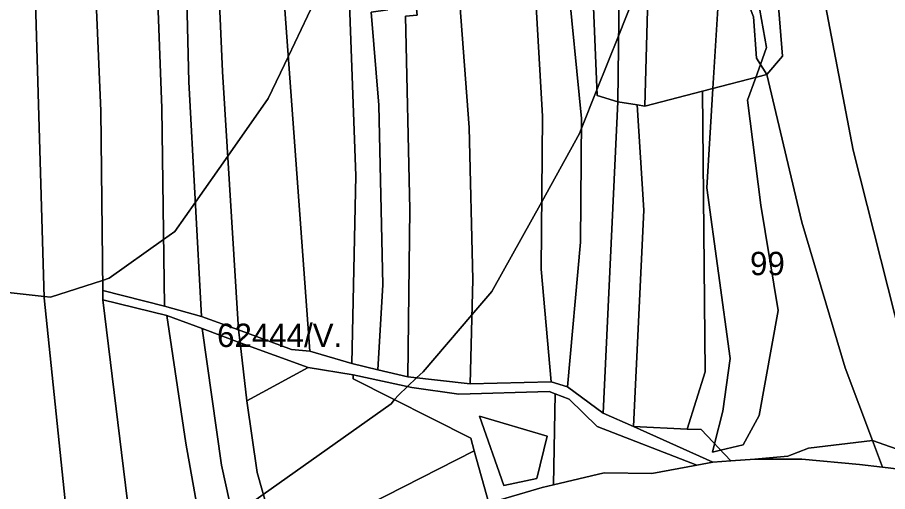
# Model space of a CAD drawing. Extents: x -502026 to -497664, y -1143484 to -1138019.
# Drawn here: x -499847.9 to -499550.1, y -1140485 to -1140322.7 of the extents above; entities that cross this region are included whole.
import ezdxf

# ---------------------------------------------------------------- set-up
doc = ezdxf.new("R2010")
doc.units = 0
for name, color, linetype in [('25', 7, 'Continuous'), ('37', 7, 'Continuous'), ('43', 7, 'Continuous'), ('55', 7, 'Continuous'), ('62', 7, 'Continuous'), ('7', 7, 'Continuous')]:
    doc.layers.add(name, color=color, linetype=linetype)

msp = doc.modelspace()

# ---------------------------------------------------------------- linework, layer by layer
at = {"layer": '25'}
msp.add_lwpolyline([(-499686.58, -1140489.01), (-499687.43, -1140489.26), (-499712.26, -1140501.49), (-499740.35, -1140520.01), (-499751.82, -1140528.09), (-499758.34, -1140505.08), (-499691.53, -1140471.05)], close=True, dxfattribs=at)
at = {"layer": '37'}
for points in [[(-499748.39, -1140442.56), (-499769.37, -1140453.89), (-499771.66, -1140434.1)], [(-499733.01, -1140445.05), (-499732.91, -1140446.38), (-499692.74, -1140466.67), (-499691.53, -1140471.05), (-499758.34, -1140505.08), (-499765.87, -1140478.52), (-499769.37, -1140453.89), (-499748.39, -1140442.56)], [(-499663.84, -1140451.56), (-499664.4, -1140482.72), (-499668.31, -1140483.66), (-499686.58, -1140489.01), (-499691.53, -1140471.05), (-499692.74, -1140466.67), (-499732.91, -1140446.38), (-499733.01, -1140445.05), (-499712.89, -1140449.42), (-499696.79, -1140451.71), (-499665.93, -1140450.77)], [(-499615.38, -1140475.96), (-499630.81, -1140478.84), (-499647.11, -1140478.54), (-499664.4, -1140482.72), (-499663.84, -1140451.56), (-499659.08, -1140453.37), (-499649.52, -1140462.72)], [(-499670.09, -1140480.49), (-499666.56, -1140466.05), (-499689.72, -1140459.19), (-499681.41, -1140482.88)], [(-499670.09, -1140480.49), (-499681.41, -1140482.88), (-499689.72, -1140459.19), (-499666.56, -1140466.05)]]:
    msp.add_lwpolyline(points, close=True, dxfattribs=at)
at = {"layer": '43'}
for points in [[(-499596.35, -1140204.84), (-499584.12, -1140216.73), (-499593.72, -1140236.53), (-499596.1, -1140251.93), (-499595.47, -1140264.79), (-499590.61, -1140280.33), (-499595.31, -1140290.27), (-499600.47, -1140311.03), (-499596.02, -1140322.53), (-499594.91, -1140336.66), (-499591.45, -1140342.31), (-499613.38, -1140347.92), (-499633.22, -1140353.08), (-499631.36, -1140287.08), (-499634.66, -1140229.73), (-499620.88, -1140231.06), (-499606.94, -1140230.49), (-499604.13, -1140197.28)], [(-499579.07, -1140255.16), (-499572.88, -1140310.74), (-499561.93, -1140368.15), (-499535.71, -1140471.44), (-499534.9, -1140474.68), (-499555.3, -1140467.53), (-499564.59, -1140442.61), (-499579.44, -1140392.82), (-499591.45, -1140342.31), (-499586.11, -1140335.99), (-499587.69, -1140315.99), (-499590.87, -1140299.36), (-499585.23, -1140286.97), (-499593.6, -1140252.66)], [(-499555.3, -1140467.53), (-499577.2, -1140470.15), (-499584.23, -1140472.85), (-499595.5, -1140473.95), (-499603.79, -1140474.51), (-499613.94, -1140463.81), (-499618.63, -1140463.6), (-499612.5, -1140444.05), (-499613.38, -1140347.92), (-499591.45, -1140342.31), (-499579.44, -1140392.82), (-499564.59, -1140442.61)], [(-499618.63, -1140463.6), (-499637, -1140462.77), (-499633.55, -1140388.66), (-499635.78, -1140352.66), (-499633.22, -1140353.08), (-499613.38, -1140347.92), (-499612.5, -1140444.05)]]:
    msp.add_lwpolyline(points, close=True, dxfattribs=at)
at = {"layer": '55'}
for points in [[(-499581.13, -1140219.7), (-499579.07, -1140255.16), (-499593.6, -1140252.66), (-499585.23, -1140286.97), (-499590.87, -1140299.36), (-499587.69, -1140315.99), (-499586.11, -1140335.99), (-499591.45, -1140342.31), (-499594.91, -1140336.66), (-499596.02, -1140322.53), (-499600.47, -1140311.03), (-499595.31, -1140290.27), (-499590.61, -1140280.33), (-499595.47, -1140264.79), (-499596.1, -1140251.93), (-499593.72, -1140236.53), (-499584.12, -1140216.73)], [(-499618.63, -1140463.6), (-499613.94, -1140463.81), (-499603.79, -1140474.51), (-499609.85, -1140474.92), (-499637, -1140462.77)], [(-499551.88, -1140476.7), (-499559.75, -1140475.77), (-499579.39, -1140473.94), (-499595.5, -1140473.95), (-499584.23, -1140472.85), (-499577.2, -1140470.15), (-499555.3, -1140467.53)], [(-499534.9, -1140474.68), (-499533.86, -1140478.84), (-499551.88, -1140476.7), (-499555.3, -1140467.53)]]:
    msp.add_lwpolyline(points, close=True, dxfattribs=at)
msp.add_lwpolyline([(-499686.58, -1140489.01), (-499668.31, -1140483.66), (-499664.4, -1140482.72), (-499647.11, -1140478.54), (-499630.81, -1140478.84), (-499615.38, -1140475.96), (-499609.85, -1140474.92), (-499603.79, -1140474.51), (-499595.5, -1140473.95), (-499579.39, -1140473.94), (-499559.75, -1140475.77), (-499551.88, -1140476.7), (-499533.86, -1140478.84)], dxfattribs=at)
at = {"layer": '62'}
for points in [[(-499605, -1140268.5), (-499609.89, -1140347.03), (-499612, -1140381), (-499604, -1140439.5), (-499606.5, -1140457.5), (-499609.3, -1140468.7), (-499610, -1140471.5), (-499607.26, -1140470.85), (-499599.5, -1140469), (-499594, -1140459), (-499587.5, -1140423), (-499593.5, -1140387), (-499598, -1140351), (-499595.21, -1140343.27), (-499593.6, -1140338.8), (-499591.5, -1140333), (-499595.5, -1140310.5)], [(-499595.5, -1140310.5), (-499591.5, -1140333), (-499593.6, -1140338.8), (-499595.21, -1140343.27), (-499598, -1140351), (-499593.5, -1140387), (-499587.5, -1140423), (-499594, -1140459), (-499599.5, -1140469), (-499607.26, -1140470.85), (-499610, -1140471.5), (-499609.3, -1140468.7), (-499606.5, -1140457.5), (-499604, -1140439.5), (-499612, -1140381), (-499609.89, -1140347.03), (-499605, -1140268.5)], [(-499735.62, -1140294.77), (-499755.15, -1140336.03), (-499762, -1140350.5), (-499775.89, -1140370.24), (-499786.96, -1140385.99), (-499794, -1140396), (-499797.84, -1140398.73), (-499816.5, -1140412), (-499818.7, -1140412.72), (-499836.5, -1140418.5), (-499838.7, -1140418.25), (-499857.26, -1140416.14), (-499858.5, -1140416), (-499872.5, -1140409.5), (-499878.74, -1140394.59), (-499884, -1140382), (-499885.5, -1140350.5), (-499881.22, -1140322.63)], [(-499881.22, -1140322.63), (-499885.5, -1140350.5), (-499884, -1140382), (-499878.74, -1140394.59), (-499872.5, -1140409.5), (-499858.5, -1140416), (-499857.26, -1140416.14), (-499838.7, -1140418.25), (-499836.5, -1140418.5), (-499818.7, -1140412.72), (-499816.5, -1140412), (-499797.84, -1140398.73), (-499794, -1140396), (-499786.96, -1140385.99), (-499775.89, -1140370.24), (-499762, -1140350.5), (-499755.15, -1140336.03), (-499735.62, -1140294.77)], [(-499850.22, -1140509.48), (-499829, -1140509), (-499828.48, -1140508.86), (-499808.38, -1140503.27), (-499785.17, -1140496.82), (-499775, -1140494), (-499774.18, -1140493.42), (-499763.74, -1140486.02), (-499720, -1140455), (-499718.77, -1140453.52), (-499717.5, -1140452), (-499714.41, -1140449.09), (-499711.25, -1140446.12), (-499709, -1140444), (-499692.31, -1140424.47), (-499685.5, -1140416.5), (-499668.44, -1140385.79), (-499655.5, -1140362.5), (-499654.91, -1140361.01), (-499649.56, -1140347.56), (-499642.11, -1140328.85), (-499637, -1140316)], [(-499637, -1140316), (-499642.11, -1140328.85), (-499649.56, -1140347.56), (-499654.91, -1140361.01), (-499655.5, -1140362.5), (-499668.44, -1140385.79), (-499685.5, -1140416.5), (-499692.31, -1140424.47), (-499709, -1140444), (-499711.25, -1140446.12), (-499714.41, -1140449.09), (-499717.5, -1140452), (-499718.77, -1140453.52), (-499720, -1140455), (-499763.74, -1140486.02), (-499774.18, -1140493.42), (-499775, -1140494), (-499785.17, -1140496.82), (-499808.38, -1140503.27), (-499828.48, -1140508.86), (-499829, -1140509), (-499850.22, -1140509.48)]]:
    msp.add_lwpolyline(points, dxfattribs=at)
at = {"layer": '7'}
for points in [[(-499642.36, -1140351.65), (-499649.48, -1140349.43), (-499654.56, -1140225.76), (-499650.43, -1140225.44), (-499650.91, -1140178.42), (-499664.08, -1140067.86), (-499660.27, -1140066.43), (-499700.5, -1139895.57), (-499688.77, -1139894.56), (-499667.83, -1139981.24), (-499649.23, -1140064.25), (-499652.92, -1140065.21), (-499644.35, -1140122.37), (-499636.61, -1140181.49), (-499635.7, -1140229.2), (-499645.61, -1140227.98), (-499641.54, -1140276.37)], [(-499658.94, -1139897.74), (-499632.6, -1140010.13), (-499602.99, -1140183.82), (-499604.13, -1140197.28), (-499606.94, -1140230.49), (-499620.88, -1140231.06), (-499634.66, -1140229.73), (-499631.36, -1140287.08), (-499633.22, -1140353.08), (-499635.78, -1140352.66), (-499642.36, -1140351.65), (-499641.54, -1140276.37), (-499645.61, -1140227.98), (-499635.7, -1140229.2), (-499636.61, -1140181.49), (-499644.35, -1140122.37), (-499652.92, -1140065.21), (-499649.23, -1140064.25), (-499667.83, -1139981.24), (-499688.77, -1139894.56)], [(-499665.18, -1140447.44), (-499692.91, -1140448.17), (-499692.01, -1140412.45), (-499693.28, -1140360.38), (-499696.45, -1140317.99), (-499689.31, -1140315.45), (-499695.43, -1140245.52), (-499695.02, -1140174.12), (-499702.32, -1140113.19), (-499713.75, -1140033.22), (-499741.2, -1139900.96), (-499721.71, -1139898.05), (-499715.33, -1139930.38), (-499697.56, -1140005), (-499686.29, -1140067.78), (-499675.35, -1140174.94), (-499676.3, -1140192.56), (-499674.08, -1140210.66), (-499678.84, -1140211.45), (-499672.17, -1140287.12), (-499668.13, -1140356.57), (-499668.68, -1140408.88)], [(-499659.65, -1140449.16), (-499665.18, -1140447.44), (-499668.68, -1140408.88), (-499668.13, -1140356.57), (-499672.17, -1140287.12), (-499678.84, -1140211.45), (-499674.08, -1140210.66), (-499676.3, -1140192.56), (-499675.35, -1140174.94), (-499686.29, -1140067.78), (-499697.56, -1140005), (-499715.33, -1139930.38), (-499721.71, -1139898.05), (-499711.37, -1139896.51), (-499682.64, -1140017.7), (-499671.22, -1140095.49), (-499669.32, -1140126.68), (-499663.6, -1140177.4), (-499662.33, -1140219.23), (-499666.7, -1140219.76), (-499659.72, -1140307.52), (-499654.88, -1140357.36), (-499655.19, -1140399.67)], [(-499642.36, -1140351.65), (-499647.39, -1140458.2), (-499659.65, -1140449.16), (-499655.19, -1140399.67), (-499654.88, -1140357.36), (-499659.72, -1140307.52), (-499666.7, -1140219.76), (-499662.33, -1140219.23), (-499663.6, -1140177.4), (-499669.32, -1140126.68), (-499671.22, -1140095.49), (-499682.64, -1140017.7), (-499711.37, -1139896.51), (-499700.5, -1139895.57), (-499660.27, -1140066.43), (-499664.08, -1140067.86), (-499650.91, -1140178.42), (-499650.43, -1140225.44), (-499654.56, -1140225.76), (-499649.48, -1140349.43)], [(-499692.91, -1140448.17), (-499714.31, -1140445.78), (-499713.59, -1140388.48), (-499715.1, -1140322.28), (-499711.05, -1140321.92), (-499714.78, -1140284.73), (-499720.73, -1140205.55), (-499717.24, -1140171.1), (-499727.24, -1140096.01), (-499735.33, -1140037.11), (-499741.52, -1140004.09), (-499751.51, -1139957.18), (-499760.64, -1139909.17), (-499741.2, -1139900.96), (-499713.75, -1140033.22), (-499702.32, -1140113.19), (-499695.02, -1140174.12), (-499695.43, -1140245.52), (-499689.31, -1140315.45), (-499696.45, -1140317.99), (-499693.28, -1140360.38), (-499692.01, -1140412.45)], [(-499714.31, -1140445.78), (-499724.58, -1140443.33), (-499722.79, -1140414.2), (-499724.14, -1140352.72), (-499726.84, -1140320.97), (-499721.13, -1140320.18), (-499729.14, -1140230.39), (-499728.5, -1140169.67), (-499737.39, -1140089.58), (-499751.99, -1140006.08), (-499771.13, -1139913.23), (-499760.64, -1139909.17), (-499751.51, -1139957.18), (-499741.52, -1140004.09), (-499735.33, -1140037.11), (-499727.24, -1140096.01), (-499717.24, -1140171.1), (-499720.73, -1140205.55), (-499714.78, -1140284.73), (-499711.05, -1140321.92), (-499715.1, -1140322.28), (-499713.59, -1140388.48)], [(-499724.58, -1140443.33), (-499733.43, -1140441.21), (-499732.07, -1140376.95), (-499734.38, -1140314.87), (-499739.06, -1140239.27), (-499739.69, -1140169.1), (-499747.63, -1140090.36), (-499759.37, -1140019.32), (-499780.77, -1139916.96), (-499771.13, -1139913.23), (-499751.99, -1140006.08), (-499737.39, -1140089.58), (-499728.5, -1140169.67), (-499729.14, -1140230.39), (-499721.13, -1140320.18), (-499726.84, -1140320.97), (-499724.14, -1140352.72), (-499722.79, -1140414.2)], [(-499768.1, -1140094.17), (-499759.53, -1140166.88), (-499761.11, -1140227.04), (-499756.67, -1140315.27), (-499747.76, -1140436.95), (-499754.1, -1140436.43), (-499772.17, -1140429.67), (-499777.7, -1140341.23), (-499781.43, -1140255.95), (-499781.27, -1140205.95), (-499780.47, -1140164.43), (-499791.42, -1140080.05), (-499821.08, -1139922.92), (-499799.6, -1139920.48), (-499772.22, -1140064.8)], [(-499772.17, -1140429.67), (-499784.84, -1140425.1), (-499789.2, -1140344.82), (-499792.37, -1140214.01), (-499792.06, -1140162.89), (-499806.66, -1140058.15), (-499833.83, -1139926.07), (-499821.08, -1139922.92), (-499791.42, -1140080.05), (-499780.47, -1140164.43), (-499781.27, -1140205.95), (-499781.43, -1140255.95), (-499777.7, -1140341.23)], [(-499784.84, -1140425.1), (-499797.53, -1140421.54), (-499798.44, -1140353.77), (-499803.48, -1140220.36), (-499803.17, -1140161.62), (-499817.45, -1140057.07), (-499827.6, -1140016.14), (-499845.3, -1139929.22), (-499833.83, -1139926.07), (-499806.66, -1140058.15), (-499792.06, -1140162.89), (-499792.37, -1140214.01), (-499789.2, -1140344.82)], [(-499797.53, -1140421.54), (-499818.67, -1140416.18), (-499819.27, -1140354.7), (-499823.56, -1140256.04), (-499823.56, -1140159.53), (-499843.55, -1140042.14), (-499858.47, -1139976.76), (-499866.12, -1139934.07), (-499845.3, -1139929.22), (-499827.6, -1140016.14), (-499817.45, -1140057.07), (-499803.17, -1140161.62), (-499803.48, -1140220.36), (-499798.44, -1140353.77)], [(-499818.67, -1140416.18), (-499818.64, -1140419.42), (-499807.69, -1140508.94), (-499796.44, -1140559.09), (-499797.53, -1140559.84), (-499816.74, -1140573.4), (-499830.44, -1140498.11), (-499838.69, -1140418.67), (-499841.78, -1140313.52), (-499844.58, -1140207.46), (-499844.53, -1140157.68), (-499862.01, -1140041.94), (-499884.38, -1139938.41), (-499866.12, -1139934.07), (-499858.47, -1139976.76), (-499843.55, -1140042.14), (-499823.56, -1140159.53), (-499823.56, -1140256.04), (-499819.27, -1140354.7)], [(-499816.74, -1140573.4), (-499838.34, -1140585.89), (-499851.71, -1140499.91), (-499855.86, -1140449.52), (-499863.55, -1140266.72), (-499864.57, -1140154.99), (-499880.85, -1140048.12), (-499891.36, -1139996.58), (-499904.88, -1139943.27), (-499884.38, -1139938.41), (-499862.01, -1140041.94), (-499844.53, -1140157.68), (-499844.58, -1140207.46), (-499841.78, -1140313.52), (-499838.69, -1140418.67), (-499830.44, -1140498.11)], [(-499733.43, -1140441.21), (-499747.76, -1140436.95), (-499756.67, -1140315.27), (-499761.11, -1140227.04), (-499759.53, -1140166.88), (-499768.1, -1140094.17), (-499747.63, -1140090.36), (-499739.69, -1140169.1), (-499739.06, -1140239.27), (-499734.38, -1140314.87), (-499732.07, -1140376.95)], [(-499471.41, -1140490.9), (-499482.59, -1140488.49), (-499517.78, -1140478.27), (-499535.71, -1140471.44), (-499561.93, -1140368.15), (-499572.88, -1140310.74), (-499579.07, -1140255.16), (-499581.13, -1140219.7), (-499568.5, -1140203.42), (-499564.32, -1140188.5), (-499560.74, -1140173.79), (-499542.64, -1140151.17), (-499540.61, -1140134.38), (-499533.92, -1140191), (-499525.12, -1140254.6), (-499516.16, -1140294.65), (-499502.11, -1140345.81), (-499473.66, -1140470.69)], [(-499635.78, -1140352.66), (-499633.55, -1140388.66), (-499637, -1140462.77), (-499647.39, -1140458.2), (-499642.36, -1140351.65)], [(-499797.53, -1140421.54), (-499784.84, -1140425.1), (-499772.17, -1140429.67), (-499771.66, -1140434.1), (-499784.68, -1140429.22), (-499796.74, -1140424.71), (-499818.64, -1140419.42), (-499818.67, -1140416.18)], [(-499796.74, -1140424.71), (-499790.24, -1140468.45), (-499776.51, -1140545.34), (-499796.44, -1140559.09), (-499807.69, -1140508.94), (-499818.64, -1140419.42)], [(-499784.68, -1140429.22), (-499778.02, -1140475.91), (-499764.61, -1140537.09), (-499767.05, -1140538.81), (-499776.51, -1140545.34), (-499790.24, -1140468.45), (-499796.74, -1140424.71)], [(-499771.66, -1140434.1), (-499769.37, -1140453.89), (-499765.87, -1140478.52), (-499758.34, -1140505.08), (-499751.82, -1140528.09), (-499764.61, -1140537.09), (-499778.02, -1140475.91), (-499784.68, -1140429.22)], [(-499747.76, -1140436.95), (-499733.43, -1140441.21), (-499724.58, -1140443.33), (-499714.31, -1140445.78), (-499692.91, -1140448.17), (-499665.18, -1140447.44), (-499659.65, -1140449.16), (-499647.39, -1140458.2), (-499637, -1140462.77), (-499609.85, -1140474.92), (-499615.38, -1140475.96), (-499649.52, -1140462.72), (-499659.08, -1140453.37), (-499663.84, -1140451.56), (-499665.93, -1140450.77), (-499696.79, -1140451.71), (-499712.89, -1140449.42), (-499733.01, -1140445.05), (-499748.39, -1140442.56), (-499771.66, -1140434.1), (-499772.17, -1140429.67), (-499754.1, -1140436.43)]]:
    msp.add_lwpolyline(points, close=True, dxfattribs=at)

# ---------------------------------------------------------------- texts
at = {"layer": '62'}
for s, p in [('99', (-499597.18, -1140410.95)), ('62444/V.', (-499779.53, -1140435.52))]:
    msp.add_text(s, height=8, dxfattribs=at).set_placement(p)

doc.saveas('drawing.dxf')
